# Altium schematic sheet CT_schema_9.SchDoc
size 371 x 245 mm
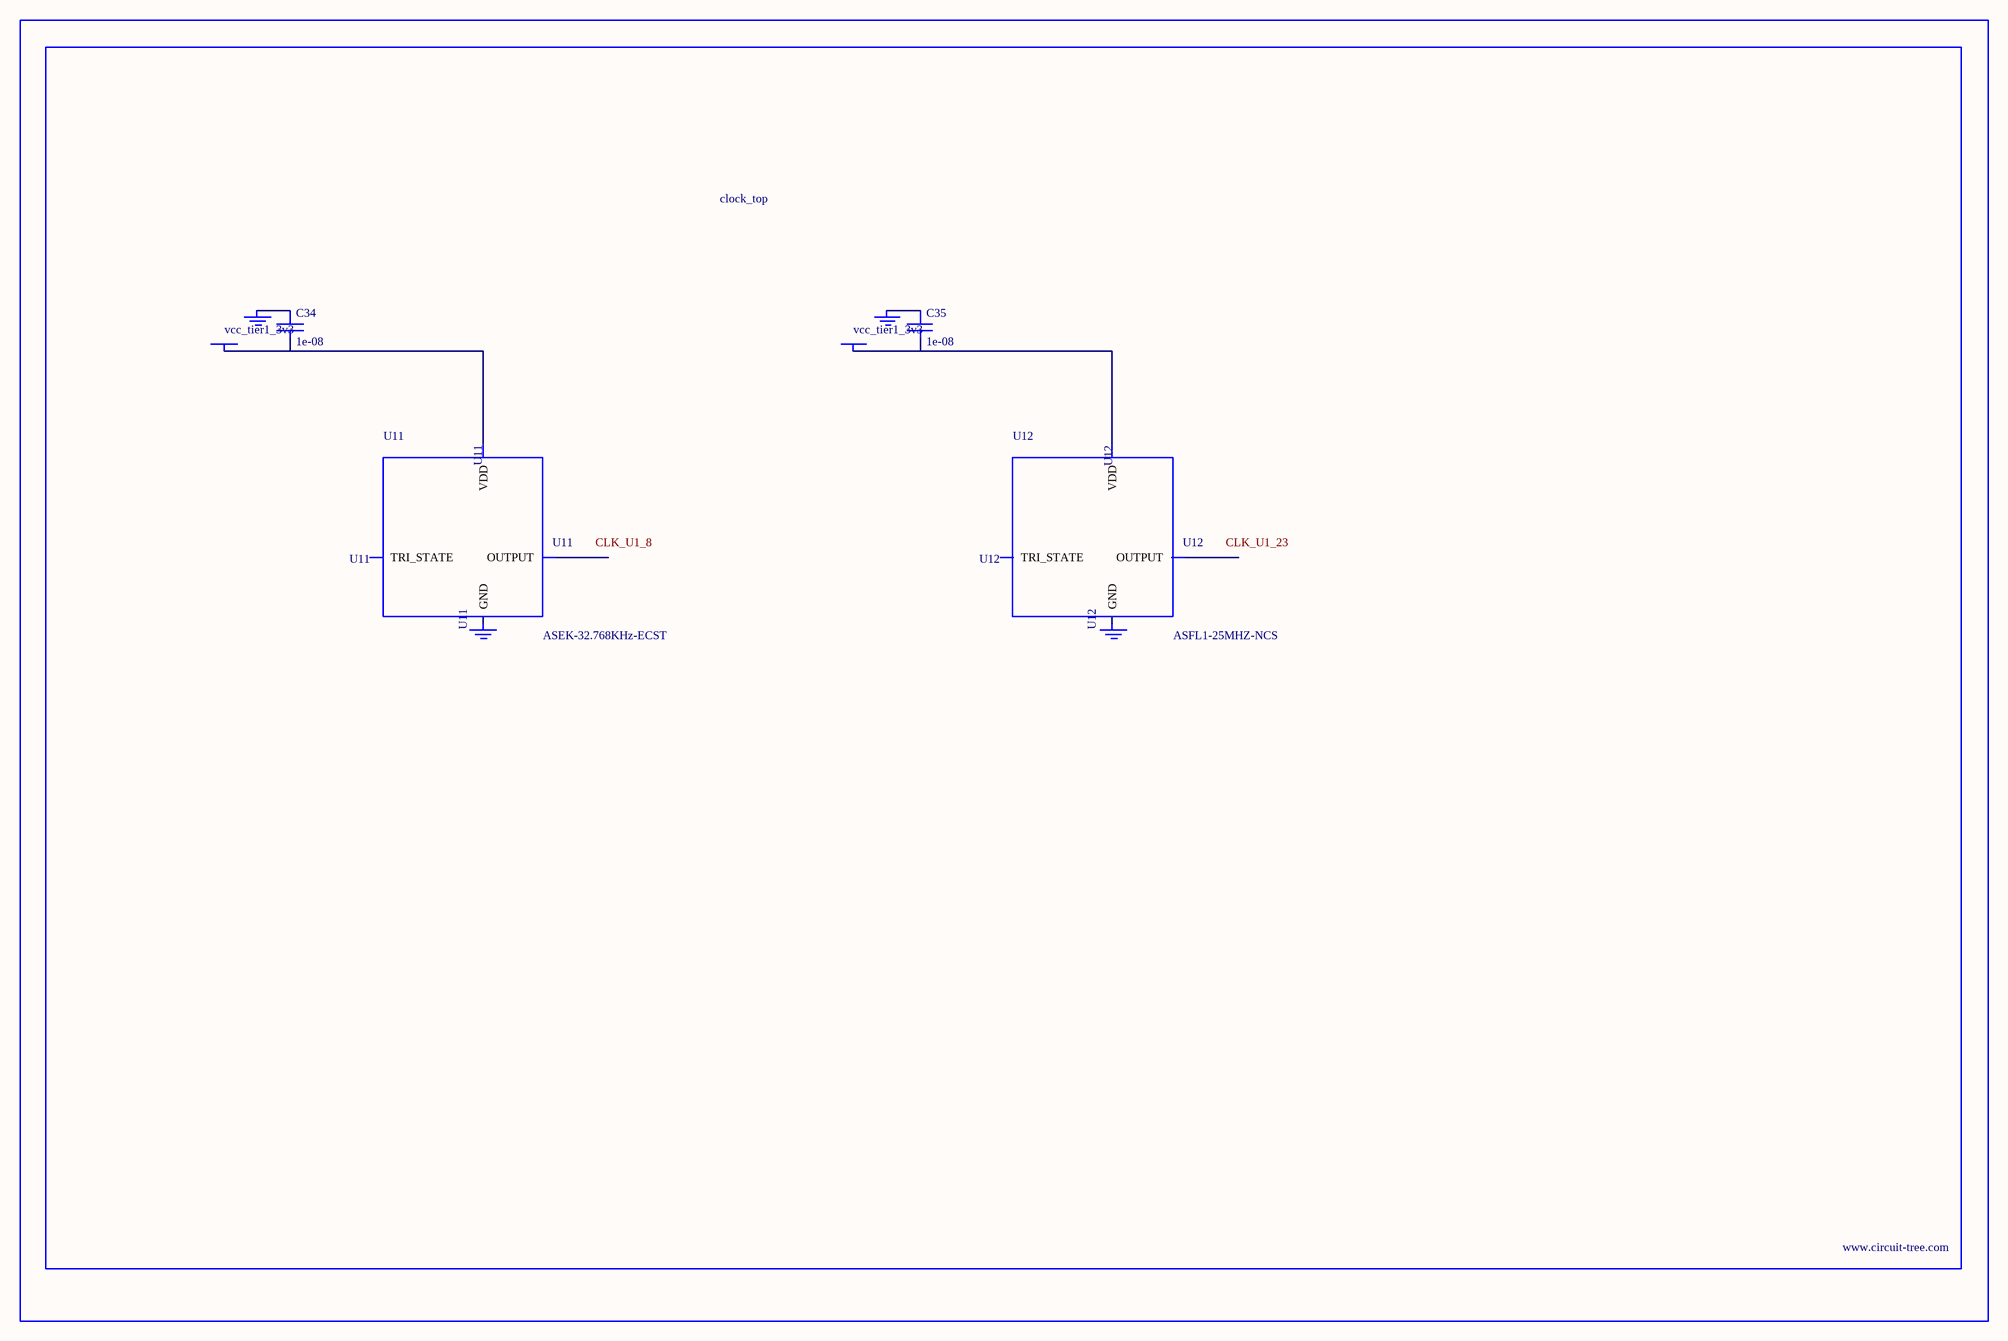
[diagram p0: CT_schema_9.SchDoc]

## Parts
BORDER8  (no value)
C34  1e-08  [C0402]
C35  1e-08  [C0402]
GND_INSTANCE_8_0  (no value)
GND_INSTANCE_8_1  (no value)
GND_INSTANCE_8_2  (no value)
GND_INSTANCE_8_3  (no value)
POWER_INSTANCE_8_0  vcc_tier1_3v3
POWER_INSTANCE_8_1  vcc_tier1_3v3
U11  ASEK-32.768KHz-ECST  [ASEK]
U12  ASFL1-25MHZ-NCS  [ASFL1]

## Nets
NetC34_1: C34.1 GND_INSTANCE_8_0.0(GND)
NetC34_2: C34.2 POWER_INSTANCE_8_0.0(PWR) U11.4(VDD)
NetC35_1: C35.1 GND_INSTANCE_8_2.0(GND)
NetC35_2: C35.2 POWER_INSTANCE_8_1.0(PWR) U12.4(VDD)

Not connected (* = marked no-connect by the designer): GND_INSTANCE_8_1 0(GND); GND_INSTANCE_8_3 0(GND); U11 1(TRI_STATE) 2(GND) 3(OUTPUT); U12 1(TRI_STATE) 2(GND) 3(OUTPUT)

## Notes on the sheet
- Labels drawn without touching a wire or pin: CLK_U1_8, CLK_U1_23

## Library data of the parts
BORDER8 = BORDER_PAGE8
C34 C35 = C0402C103K3RAC
GND_INSTANCE_8_0-GND_INSTANCE_8_3 = GND
POWER_INSTANCE_8_0 POWER_INSTANCE_8_1 = PWR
